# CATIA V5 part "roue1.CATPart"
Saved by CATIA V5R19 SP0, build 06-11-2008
Part number: roue1
Bounding box of the stored display mesh (mm): x -107.981 to 31.981, y -30 to 30, z -319.98 to 200
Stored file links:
  I:\yyang\yyang\roue1.CATPart
  I:\yyang\yyang\yyang.CATProduct
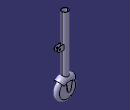
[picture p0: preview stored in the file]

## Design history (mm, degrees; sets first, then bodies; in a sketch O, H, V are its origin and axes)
External parameters (linked from other documents)
  `External.angle de l'antiboue` = 40 deg
  `External.rayon1 de l'antiboue` = 30 mm
  `External.rayon2 de l'antiboue` = 25 mm
  `External.epaisseur du pivot` = 2 mm
  `External.demi-distance entre les des pivot` = 9 mm
  `External.rayon du trou des liaisons` = 5 mm
Set1
  Plane1: linked copy from another document
  Point1 to Point3: linked copy from another document
  Plane2: linked copy from another document
  Point4: linked copy from another document
  Point5: linked copy from another document
  Line1: linked copy from another document
  Plane3: linked copy from another document
  Point6 to Point8: linked copy from another document
  Line2: linked copy from another document
  Plane4: linked copy from another document
  Point9: linked copy from another document
  Point10: linked copy from another document
Body1 (main body)
  Sketch1 on Plane1, origin (-38, 0, 0), H (0, 1, 0), V (0, 0, 1)
    construction line L1 (0, -196) -> (0, -304)
    point P1 (0, -196)
    point P2 (0, -304)
    line L2 (16, -196) -> (16, -250)
    line L3 (-16, -250) -> (-16, -196)
    arc A1 centre (0, -196) radius 16 from (-16, -196) to (16, -196) cw
    reference projected point E1 (0, -196) from Point1
    reference projected point E2 (0, -304) from Point2
    reference projected point E3 (16, -250) from Point3
    line L4 (16, -250) -> (-16, -250)
    vertical: L1 V
    tangency: A1 L2, A1 L3
    coincidence: P1 E1, P2 E2, E3 L2
    horizontal: L4 H
  Shaft1: profile Sketch1, axis Line1, angle 360
  Sketch2 on Plane3, origin (0, 0, 0), H (-1, 0, 0), V (0, 0, 1)
    circle A1 centre (38, -250) radius 5
    point P1 (38, -250)
    reference projected point E1 (38, -250) from Point6
    reference projected point E2 (38, -245) from Point7
    coincidence: P1 E1, A1 E2
  Pad1: profile Sketch2, direction (0, 1, 0), length 25 {= `External.rayon2 de l'antiboue`}, mirrored extent
  Sketch3 on end face of Pad1, origin (0, 25, 0), H (-1, 0, 0), V (0, 0, 1)
    arc A1 centre (38, -250) radius 10 from (28.1519, -251.7365) to (47.8481, -251.7365) ccw
    point P1 (38, -250)
    reference projected point E1 (38, -250) from Point6
    arc A2 centre (38, -250) radius 54 from (57.0629, -199.4767) to (18.9371, -199.4767) ccw
    point P2 (38, -250)
    reference projected point E2 (38, -250) from Point6
    reference projected point E3 (38, -196) from Point1
    line L1 (18.9371, -199.4767) -> (28.1519, -251.7365)
    line L2 (57.0629, -199.4767) -> (47.8481, -251.7365)
    angle V L2 = 10
    radius A1 = 10
    angle L1 V = 10
    coincidence: P1 E1, P2 E2, A2 E3
    tangency: L1 A1, L2 A1
  Pad2: profile Sketch3, direction (0, 1, 0), length 5 {= `External.rayon1 de l'antiboue` -`External.rayon2 de l'antiboue`}
  Mirror1: of Pad2, about Plane3
  Sketch4 on Plane3, origin (0, 0, 0), H (-1, 0, 0), V (0, 0, 1)
    arc A1 centre (-7, 0) radius 16 from (-7, 16) to (-7, -16) ccw
    point P1 (-7, 0)
    reference projected point E1 (-7, 0) from Point8
    line L1 (-7, 16) -> (38, 16)
    point P2 (38, 16)
    line L2 (-7, -16) -> (38, -16)
    point P4 (38, -16)
    reference projected line E2 (38, 0) -> (38, 450) from Line2
    reference projected line E3 (38, 0) -> (38, 450) from Line2
    line L3 (38, 16) -> (38, -16)
    circle A2 centre (-7, 0) radius 5
    point P6 (-7, 0)
    reference projected point E4 (-7, 0) from Point8
    reference projected point E5 (-7, 0) from Point8
    radius A1 = 16
    distance E5 A2 = 5 {= `External.rayon du trou des liaisons`}
    coincidence: P1 E1, P2 E2, P4 E3, P6 E4
    horizontal: L1 H, L2 H
    tangency: L1 A1, L2 A1
    vertical: L3 V
  Pad3: profile Sketch4, direction (0, 1, 0), length 11 {= `External.epaisseur du pivot`+`External.demi-distance entre les des pivot`}, mirrored extent
  Sketch5 on Plane3, origin (0, 0, 0), H (-1, 0, 0), V (0, 0, 1)
    line L1 (-23, 16) -> (38, 16)
    line L2 (38, 16) -> (38, -16)
    line L3 (38, -16) -> (-23, -16)
    line L4 (-23, -16) -> (-23, 16)
    reference projected line E1 (38, 0) -> (38, 450) from Line2
    reference projected line E2 (0, 16) -> (-38, 16) from edge [face of Pad3 from Sketch4.L1 | end face of Pad3]
    reference projected line E3 (-38, -16) -> (0, -16) from edge [face of Pad3 from Sketch4.L2 | end face of Pad3]
    reference projected arc E4 centre (-7, 0) radius 16 from (-7, 16) to (-7, -16) ccw from edge [face of Pad3 from Sketch4.A1 | end face of Pad3]
    horizontal: L1 H, L3 H
    vertical: L2 V, L4 V
    coincidence: L2 E1, L1 E2, L3 E3
    tangency: L4 E4
  Pocket1: profile Sketch5, direction (0, -1, 0), length 9 {= `External.demi-distance entre les des pivot`}, mirrored extent
  Sketch6 on Plane4, origin (0, 0, 200), H (1, 0, 0), V (0, 1, 0)
    circle A1 centre (-38, 0) radius 18
    point P1 (-38, 0)
    reference projected point E1 (-38, 0) from Point1
    reference projected point E2 (-20, 0) from Point10
    coincidence: P1 E1, A1 E2
  Pocket2: profile Sketch6, direction (0, 0, -1), up to face of Pad3 from Sketch4.L2
  Sketch7 on Plane1, origin (-38, 0, 0), H (0, 1, 0), V (0, 0, 1)
    arc A1 centre (0, -196) radius 30 from (30, -196) to (-30, -196) ccw
    point P1 (0, -196)
    arc A2 centre (0, -196) radius 25 from (25, -196) to (-25, -196) ccw
    point P2 (0, -196)
    reference projected point E1 (0, -196) from Point1
    reference projected point E2 (0, -166) from Point5
    reference projected point E3 (0, -196) from Point1
    reference projected point E4 (0, -171) from Point4
    line L1 (-30, -196) -> (-25, -196)
    line L2 (25, -196) -> (30, -196)
    point P5 (25, -196)
    coincidence: P1 E1, A1 E2, P2 E3, A2 E4, P5 L1
    horizontal: L1 H, L2 H
  Shaft2: profile Sketch7, axis Line1, angle 40 {= `External.angle de l'antiboue`}, second angle 40 {= `External.angle de l'antiboue`}
  Sketch8 on Plane4, origin (0, 0, 200), H (1, 0, 0), V (0, 1, 0)
    circle A1 centre (-38, 0) radius 18
    point P1 (-38, 0)
    reference projected point E1 (-38, 0) from Point2
    reference projected point E2 (-20, 0) from Point10
    circle A2 centre (-38, 0) radius 21
    point P2 (-38, 0)
    reference projected point E3 (-38, 0) from Point1
    reference projected point E4 (-17, 0) from Point9
    coincidence: P1 E1, A1 E2, P2 E3, A2 E4
  Pad4: profile Sketch8, direction (0, 0, -1), up to face of Shaft2 from Sketch7.A1
Relations
  Pad1.FirstLimit.Length = `Paramètres externes\rayon2 de l'antiboue` (deactivated)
